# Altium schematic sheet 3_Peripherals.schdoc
size 309 x 223 mm; Symbol: Sheet-Symbol_A4; Device: Sheet-Symbol_A4; @Project Name: Digital_Watch_V01; @Page Count: 3; @Update Date: 2024-11-10; @Create Date: 2024-11-10; @Schematic Name: D-Watch_Sch_v1.2; @Page No: 3; @Page Name: Peripherals; Company: EasyEDA.com; Reviewed: EasyEDA; Version: V0.1; Page Size: A4; Part Number: JLCPCB-002; Drawn: EasyEDA; @Board Name: D-Watch_Board_v1.2; @Create Time: 18:08:53; @Update Time: 18:18:36
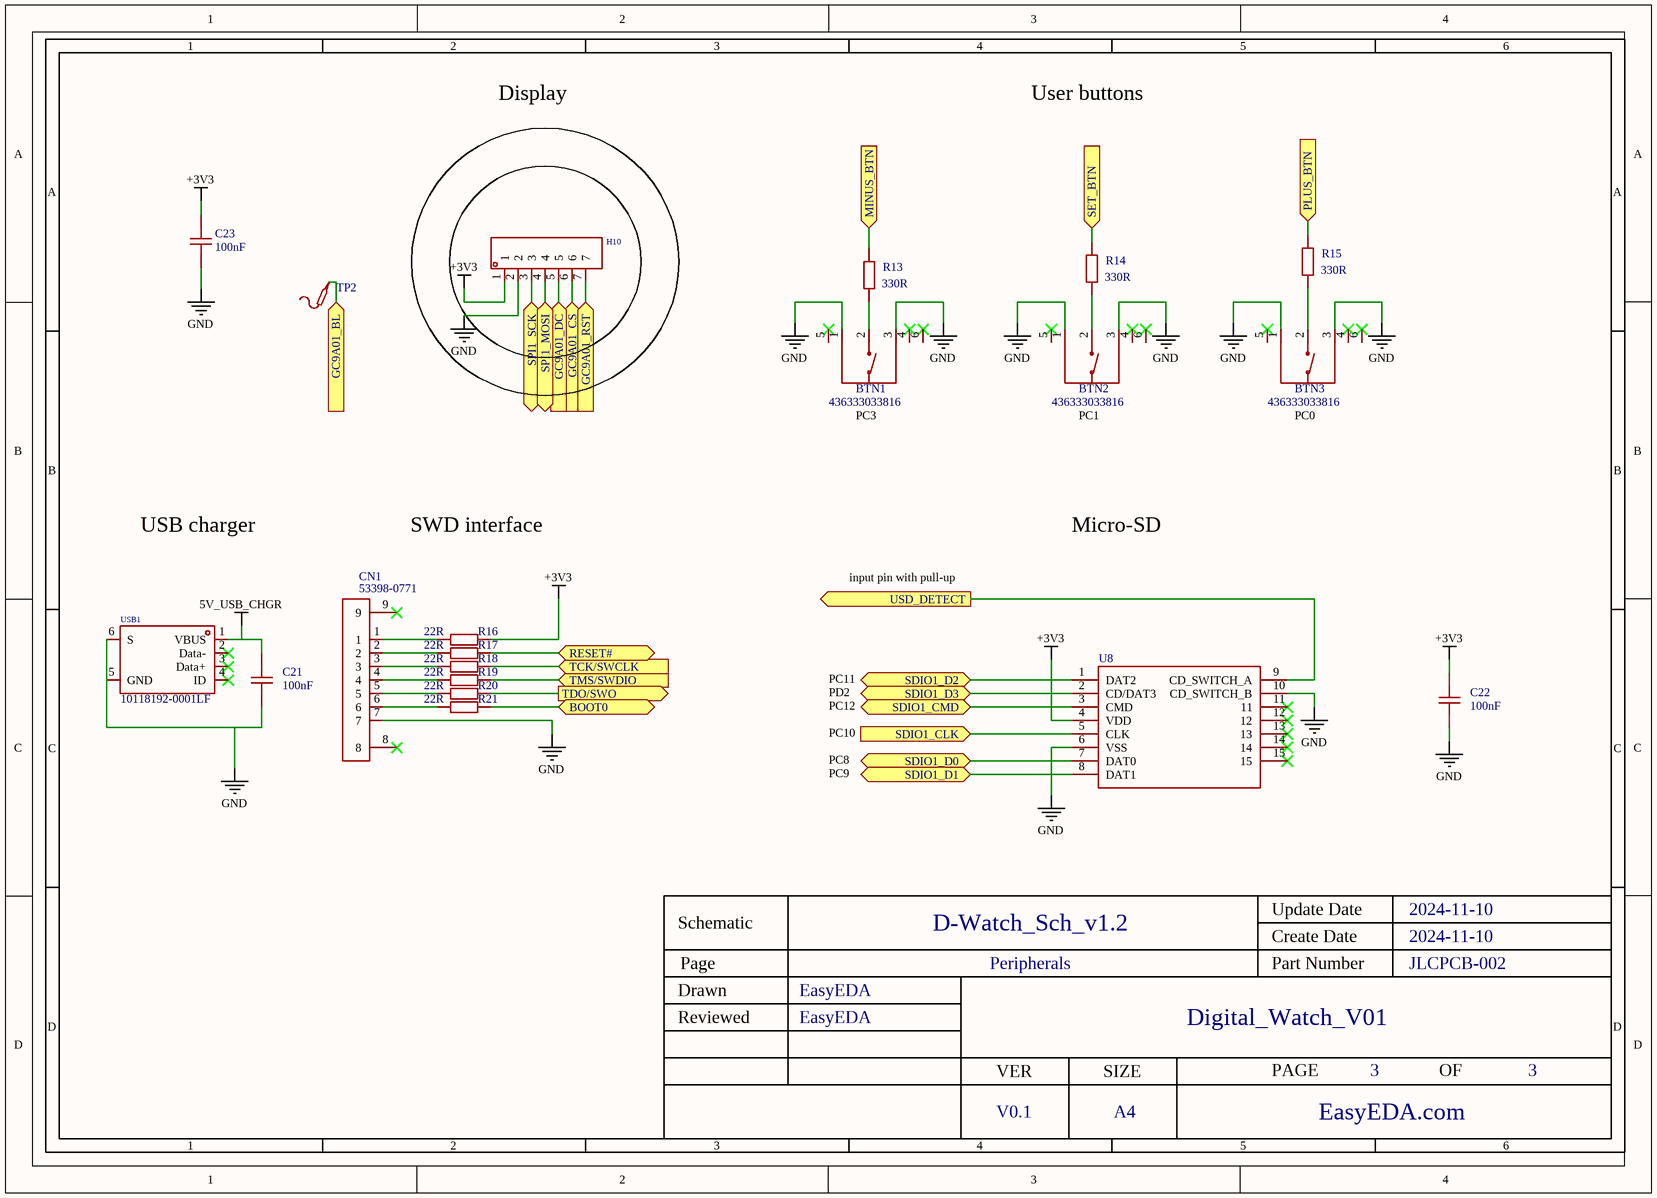
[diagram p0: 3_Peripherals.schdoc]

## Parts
BTN1  436333033816  [SW-SMD_436333033816]  (value not drawn)
BTN2  436333033816  [SW-SMD_436333033816]  (value not drawn)
BTN3  436333033816  [SW-SMD_436333033816]  (value not drawn)
C21  100nF  [C0603]  (value not drawn)
C22  100nF  [C0603]  (value not drawn)
C23  100nF  [C0603]  (value not drawn)
CN1  53398-0771  [CONN-SMD_7P-P1.25_53398-0771]  (value not drawn)
H10  HDR-F_2.54_1x7P  [HDR-TH_7P-P2.54-V-F]  (value not drawn)
R13  330R  [R0603]  (value not drawn)
R14  330R  [R0603]  (value not drawn)
R15  330R  [R0603]  (value not drawn)
R16  22R  [R0603]  (value not drawn)
R17  22R  [R0603]  (value not drawn)
R18  22R  [R0603]  (value not drawn)
R19  22R  [R0603]  (value not drawn)
R20  22R  [R0603]  (value not drawn)
R21  22R  [R0603]  (value not drawn)
TP2  Test-Point  [Test-Point-0.5mm]  (value not drawn)
U8  DM3BT-DSF-PEJS_  [DM3BTDSFPEJS]  (value not drawn)
USB1  10118192-0001LF  [MICRO-USB-SMD_10118192-0001LF_1]  (value not drawn)

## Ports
BOOT0 (bidir), GC9A01_BL (in), GC9A01_CS (in), GC9A01_DC (in), GC9A01_RST (in), MINUS_BTN (in), PLUS_BTN (in), RESET# (bidir), SDIO1_CLK (in), SDIO1_CMD (bidir), SDIO1_D0 (bidir), SDIO1_D1 (bidir), SDIO1_D2 (bidir), SDIO1_D3 (bidir), SET_BTN (in), SPI1_MOSI (bidir), SPI1_SCK (bidir), TCK/SWCLK (in), TDO/SWO (out), TMS/SWDIO (in), USD_DETECT (out)

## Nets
5V_USB_CHGR: C21.1 USB1.1(VBUS)
+3V3: C22.1 C23.1 H10.1 R16.1 U8.4(VDD)
GND: BTN1.1 BTN1.3 BTN2.1 BTN2.3 BTN3.1 BTN3.3 C21.2 C22.2 C23.2 CN1.7 H10.2 U8.6(VSS) U8.10(CD_SWITCH_B) USB1.5(GND) USB1.6(S)
BOOT0: R21.1 ; port BOOT0
GC9A01_BL: TP2.1 ; port GC9A01_BL
GC9A01_CS: H10.6 ; port GC9A01_CS
GC9A01_DC: H10.5 ; port GC9A01_DC
GC9A01_RST: H10.7 ; port GC9A01_RST
MINUS_BTN: R13.2 ; port MINUS_BTN
PLUS_BTN: R15.2 ; port PLUS_BTN
RESET#: R17.1 ; port RESET#
SDIO1_CLK: U8.5(CLK) ; port SDIO1_CLK
SDIO1_CMD: U8.3(CMD) ; port SDIO1_CMD
SDIO1_D0: U8.7(DAT0) ; port SDIO1_D0
SDIO1_D1: U8.8(DAT1) ; port SDIO1_D1
SDIO1_D2: U8.1(DAT2) ; port SDIO1_D2
SDIO1_D3: U8.2(CD/DAT3) ; port SDIO1_D3
SET_BTN: R14.2 ; port SET_BTN
SPI1_MOSI: H10.4 ; port SPI1_MOSI
SPI1_SCK: H10.3 ; port SPI1_SCK
TCK/SWCLK: R18.1 ; port TCK/SWCLK
TDO/SWO: R20.1 ; port TDO/SWO
TMS/SWDIO: R19.1 ; port TMS/SWDIO
USD_DETECT: U8.9(CD_SWITCH_A) ; port USD_DETECT
NetBTN1_2: BTN1.2 R13.1
NetBTN2_2: BTN2.2 R14.1
NetBTN3_2: BTN3.2 R15.1
NetCN1_1: CN1.1 R16.2
NetCN1_2: CN1.2 R17.2
NetCN1_3: CN1.3 R18.2
NetCN1_4: CN1.4 R19.2
NetCN1_5: CN1.5 R20.2
NetCN1_6: CN1.6 R21.2

Not connected (* = marked no-connect by the designer): BTN1 4* 5* 6*; BTN2 4* 5* 6*; BTN3 4* 5* 6*; CN1 8* 9*; U8 11* 12* 13* 14* 15*; USB1 2(Data-)* 3(Data+)* 4(ID)*

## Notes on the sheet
- Display
- User buttons
- PC3
- PC1
- PC0
- USB charger
- SWD interface
- Micro-SD
- input pin with pull-up
- PC11
- PC10
- PC12
- PD2
- PC8
- PC9

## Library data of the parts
BTN1-BTN3 = 436333033816: Circuit:SPST - normally open Actuator Style:Round Button Operating Force:160gf Mounting Style:Standing paste Contact Current:50mA Voltage Rating (DC):12V Pin Style:SMDSplicing Operating Temperature:-40℃~+85℃ Operating Temperature:-40℃~+85℃; Manufacturer: Wurth(伍尔特); Add into BOM: yes; Operating Force: 160gf; Contact Current: 50mA; Voltage Rating (DC): 12V
C21-C23 = GCJ188R71C104KA01D: Capacitance: Tolerance:±10% Tolerance:±10% Voltage Rated: Temperature Coefficient:; Manufacturer: muRata(村田); Add into BOM: yes; Tolerance: ±10%
CN1 = 53398-0771: Manufacturer: MOLEX; Manufacturer Part: 533980771; Convert to PCB: yes
H10 = HDR-F_2.54_1x7P: Manufacturer: Ckmtw(灿科盟); Manufacturer Part: B-2200S07P-A120; Symbol: 220S-1*7P H=8.5MM Ytype Gold-plated; Convert to PCB: yes
R13-R21 = Res_0603: Symbol: Res; Convert to PCB: yes
TP2 = Test-Point: Test Point 测试点; Add into BOM: yes
U8 = DM3BT-DSF-PEJS_: Add into BOM: yes
USB1 = 10118192-0001LF: Connector Type:Micro-B Standard:USB 2.0 Gender:Female Number of Ports:1 Number of Contacts:5P Mounting Style:卧贴 Current Rating - Power (Max):- Operating Temperature Range:-30℃~+80℃ Operating Temperature Range:-30℃~+80℃; Manufacturer: Amphenol; Add into BOM: yes; Gender: Female; Number of Ports: 1; Number of Contacts: 5P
